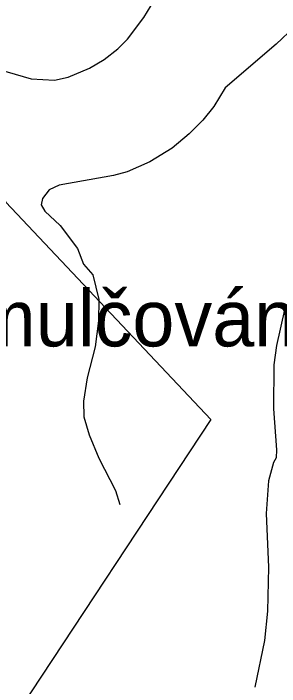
# Model space of a CAD drawing. Extents: x -662620 to -656370, y -1067090 to -1062990.
# Drawn here: x -657850.4 to -657732.7, y -1066290.2 to -1065992.7 of the extents above; entities that cross this region are included whole.
import ezdxf

# ---------------------------------------------------------------- set-up
doc = ezdxf.new("R2010")
doc.units = 0
doc.layers.add('Agrotechnicka_opatreni_hrazkovani_a_dulkovani__mulcovani', color=7, linetype='Continuous')
doc.layers.add('VRSTEVNICE_ZÁKLADNÍ', color=7, linetype='Continuous')

msp = doc.modelspace()

# ---------------------------------------------------------------- linework, layer by layer
at = {"layer": 'Agrotechnicka_opatreni_hrazkovani_a_dulkovani__mulcovani'}
msp.add_lwpolyline([(-657947.14, -1065475.33), (-657926.1, -1065475.3), (-657857.2, -1065476.8), (-657874.4, -1065747.42), (-657896.85, -1065987.18), (-657891.46, -1066029.38), (-657853.75, -1066076.08), (-657763.05, -1066172.16), (-657851.95, -1066306.85), (-657923.42, -1066262.26), (-657921.99, -1066222.44), (-657979.46, -1066133.55), (-658044.12, -1066006.03), (-658063.87, -1065974.6), (-658066.57, -1065958.44), (-658054.89, -1065918.93), (-657975.87, -1065742.03), (-657956.12, -1065677.38), (-657948.93, -1065520.23)], close=True, dxfattribs=at)
at = {"layer": 'VRSTEVNICE_ZÁKLADNÍ'}
for points in [[(-657922.05, -1066014.25), (-657913.53, -1066009.22), (-657905.75, -1066007.38), (-657899.75, -1066007.38), (-657893.46, -1066008.38), (-657884.74, -1066011.67), (-657879.98, -1066015.75), (-657873.45, -1066016.5), (-657867.16, -1066015.67), (-657861.44, -1066016.1), (-657842.57, -1066021.53), (-657832.28, -1066022.1), (-657826.28, -1066020.81), (-657816.84, -1066016.81), (-657810.27, -1066013.1), (-657804.27, -1066008.38), (-657799.98, -1066004.09), (-657792.69, -1065994.52), (-657778.11, -1065970.5), (-657750.38, -1065928.48), (-657742.52, -1065914.76), (-657737.66, -1065902.75), (-657734.94, -1065894.18), (-657722.94, -1065847.87)], [(-657922.05, -1066014.25), (-657913.53, -1066009.22), (-657905.75, -1066007.38), (-657899.75, -1066007.38), (-657893.46, -1066008.38), (-657884.74, -1066011.67), (-657879.98, -1066015.75), (-657873.45, -1066016.5), (-657867.16, -1066015.67), (-657861.44, -1066016.1), (-657842.57, -1066021.53), (-657832.28, -1066022.1), (-657826.28, -1066020.81), (-657816.84, -1066016.81), (-657810.27, -1066013.1), (-657804.27, -1066008.38), (-657799.98, -1066004.09), (-657792.69, -1065994.52), (-657778.11, -1065970.5), (-657750.38, -1065928.48), (-657742.52, -1065914.76), (-657737.66, -1065902.75), (-657734.94, -1065894.18), (-657722.94, -1065847.87)], [(-657726.08, -1065998.52), (-657734.23, -1066006.24), (-657756.81, -1066025.53), (-657761.84, -1066033.85)], [(-657726.08, -1065998.52), (-657734.23, -1066006.24), (-657756.81, -1066025.53), (-657761.84, -1066033.85)], [(-657761.84, -1066033.85), (-657766.63, -1066039.83), (-657772.65, -1066045.85), (-657780.25, -1066052.16), (-657790.14, -1066058.32), (-657800.17, -1066062.76), (-657806.19, -1066064.34), (-657830.26, -1066068.64), (-657834.58, -1066070.6), (-657837.57, -1066074.51), (-657838.12, -1066077.23), (-657836.51, -1066080.02), (-657829.69, -1066086.41), (-657822.1, -1066096.59), (-657819.37, -1066103.46), (-657815.3, -1066108.28), (-657812.64, -1066119.09), (-657812.73, -1066128.54), (-657814.32, -1066140), (-657817.8, -1066153.77), (-657819.37, -1066164.09), (-657819.32, -1066170.99), (-657816.94, -1066178.99), (-657812.64, -1066189.31), (-657805.33, -1066203.64), (-657803.32, -1066209.81)], [(-657761.84, -1066033.85), (-657766.63, -1066039.83), (-657772.65, -1066045.85), (-657780.25, -1066052.16), (-657790.14, -1066058.32), (-657800.17, -1066062.76), (-657806.19, -1066064.34), (-657830.26, -1066068.64), (-657834.58, -1066070.6), (-657837.57, -1066074.51), (-657838.12, -1066077.23), (-657836.51, -1066080.02), (-657829.69, -1066086.41), (-657822.1, -1066096.59), (-657819.37, -1066103.46), (-657815.3, -1066108.28), (-657812.64, -1066119.09), (-657812.73, -1066128.54), (-657814.32, -1066140), (-657817.8, -1066153.77), (-657819.37, -1066164.09), (-657819.32, -1066170.99), (-657816.94, -1066178.99), (-657812.64, -1066189.31), (-657805.33, -1066203.64), (-657803.32, -1066209.81)], [(-657730.52, -1066123.67), (-657734.1, -1066139.44), (-657735.25, -1066148.04), (-657735.39, -1066167.53), (-657734.1, -1066185.59), (-657734.24, -1066189.17), (-657735.33, -1066191.27), (-657737.54, -1066199.34), (-657738.68, -1066213.68), (-657737.54, -1066237.47), (-657737.97, -1066256.96), (-657739.4, -1066269.86), (-657743.7, -1066290.49)], [(-657730.52, -1066123.67), (-657734.1, -1066139.44), (-657735.25, -1066148.04), (-657735.39, -1066167.53), (-657734.1, -1066185.59), (-657734.24, -1066189.17), (-657735.33, -1066191.27), (-657737.54, -1066199.34), (-657738.68, -1066213.68), (-657737.54, -1066237.47), (-657737.97, -1066256.96), (-657739.4, -1066269.86), (-657743.7, -1066290.49)]]:
    msp.add_lwpolyline(points, dxfattribs=at)

# ---------------------------------------------------------------- texts
at = {"layer": 'Agrotechnicka_opatreni_hrazkovani_a_dulkovani__mulcovani'}
msp.add_text('PEO 2, mulčování', height=25, dxfattribs=at).set_placement((-657985.45, -1066139.87))

doc.saveas('drawing.dxf')
